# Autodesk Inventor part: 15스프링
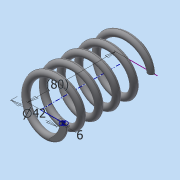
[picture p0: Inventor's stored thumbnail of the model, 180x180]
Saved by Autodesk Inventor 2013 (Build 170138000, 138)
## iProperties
Created: 2019-10
Part Number: 15스프링
Material: 일반
Document SubType Name: Modeling
Designer: dgall
Density: 1 g/cm^3
Author: dgall
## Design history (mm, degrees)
sketch "스케치1"
  geometry: L1 (21, 0)-(0, 0); L2 (0, 0)-(0, 80); L3 (0, 80)-(26.364, 80); C1 r 3 at (21, 0)
  constraints: 6 end point, 1 centre point, 1 coincident, 1 horizontal, 1 parallel, 1 perpendicular
  dimensions: "d0" = 6 diameter of C1; "d2" = 80 distance between parallel lines of L1 L3 (derived); "d3" = 42 diameter of C1.centre L2
feature "코일1" pitch "d4" = 10; turns "d6" = 5; dims "d5" = 80 (= d2), "d7" = 0, angle "d8" = 90 deg, angle "d9" = 90 deg, "d10" = 0, "d11" = 0
feature "분할1"
node "작업 평면1"
feature "분할2"
node "솔리드1"
other parameters: "d12" = 0
